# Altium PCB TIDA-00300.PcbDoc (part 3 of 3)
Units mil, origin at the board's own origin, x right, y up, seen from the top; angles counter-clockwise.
Board outline 2685 x 3089 mil, 4 copper layers (Top Layer, L2_GND-PLANE, L3_PWR-PLANE, Bottom Layer), stack 63.6 mil thick; 196 components, 87 nets, 476 pads, 171 vias.
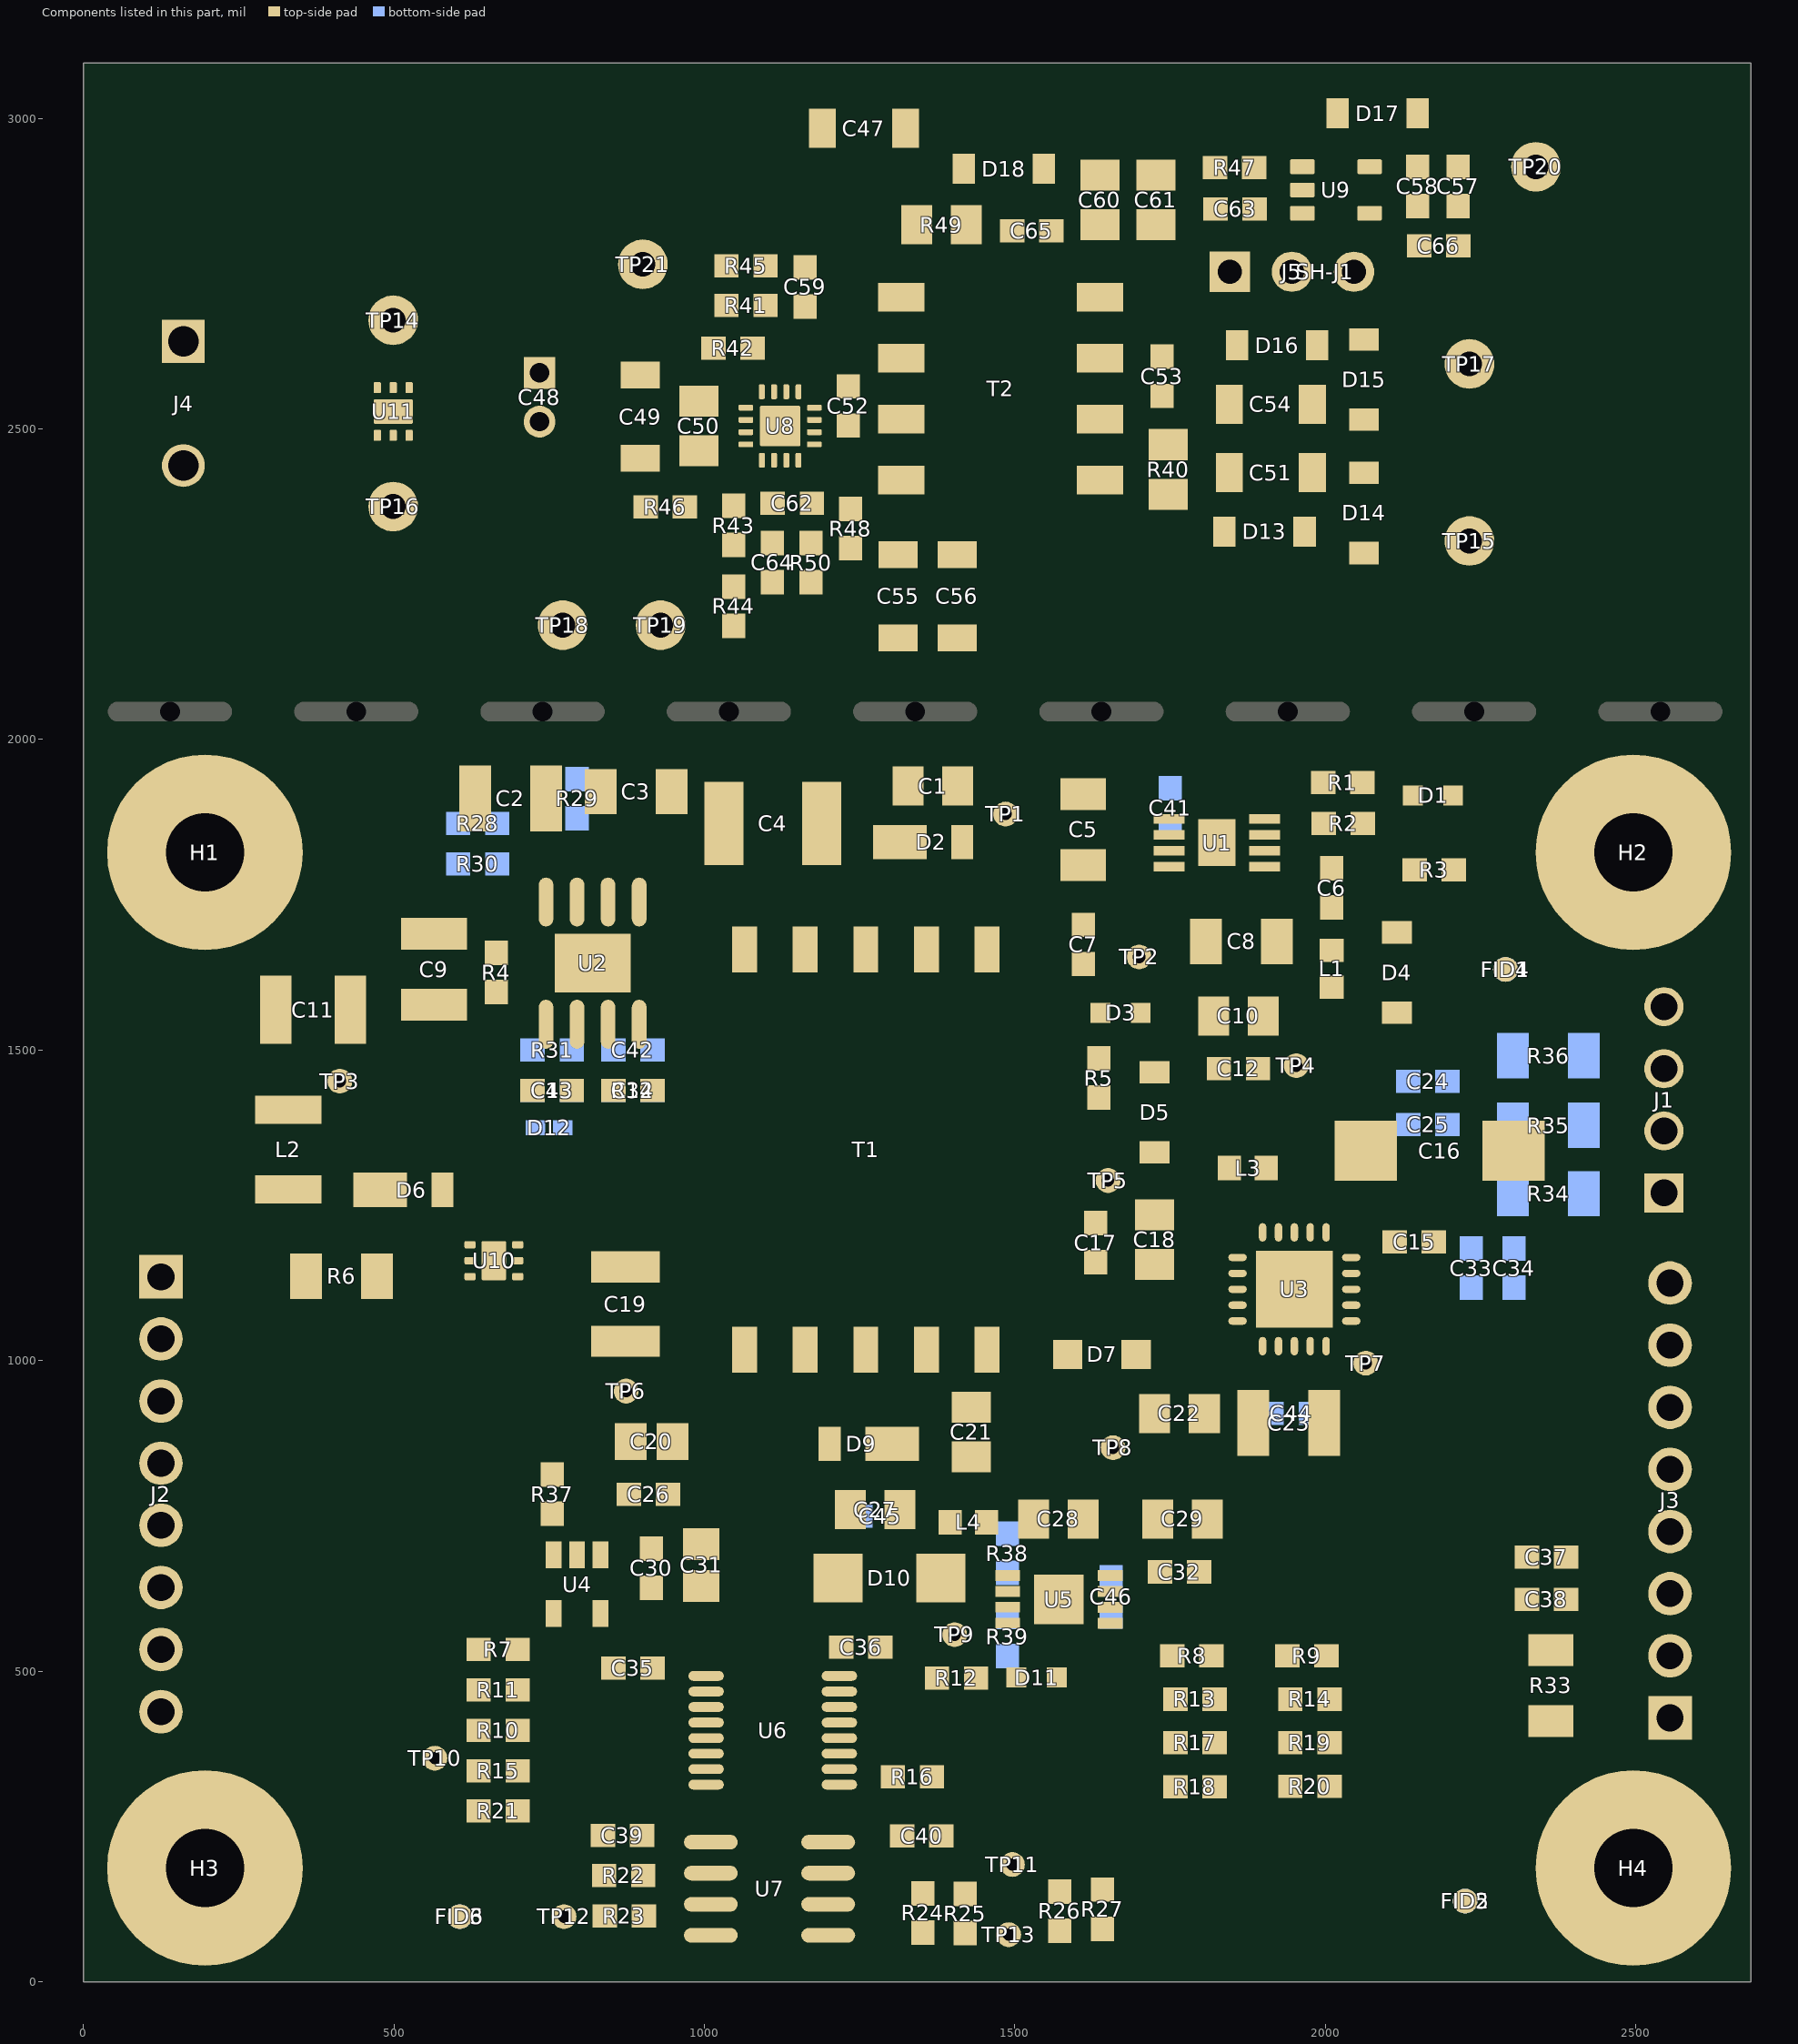
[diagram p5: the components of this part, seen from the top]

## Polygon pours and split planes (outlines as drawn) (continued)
GND_ISO on Top Layer "Top Layer-No Net 1" (hatched 90Degree grid 5 track 10, remove dead copper, pour order 64): 1830,1415 1705,1415 1700,1420 1700,1595 1760,1655 1760,1700 1800,1740 1800,1885 1770,1915 1579,1915 1579,1955 1840,1955 1855,1940 1855,1650 1840,1635 1840,1425
+6V_ISO on Top Layer "Top Layer-No Net 1" (hatched 90Degree grid 5 track 10, remove dead copper, pour order 58): 1635,565 1725,565 1755,595 1755,1043 1743,1055 1680,1055 1665,1040 1665,945 1625,905 1625,820 1660,785 1660,730 1690,700 1690,675 1685,670 1635,670 1635,650 1725,650 1735,640 1735,600 1715,580 1635,580
GND_ISO on Top Layer "Top Layer-No Net 1" (hatched 90Degree grid 5 track 10, remove dead copper, pour order 65): 1595,465 1555.67,465 1545,475.67 1545,535 1520,560 1465,560 1460,565 1460,575 1465,580 1525,580 1535,590 1535,655 1590,710 1590,770 1620,770 1620,710 1600,690 1600,470
9.3V_NON_ISO on Top Layer "Top Layer-No Net" (hatched 90Degree grid 5 track 8, remove dead copper, pour order 67): 1075,1040 1010,1040 987,1027 962,1027 935,1054 786,1053 786,801 820,759 820,670 830,660 855,660 865,670 865,730 895,760 895,910 910,925 955,925 1030,1000 1070,1000 1075,1005
GND on Top Layer "Bottom Layer-No Net" (solid, remove dead copper, pour order 40): 663,1277 647,1261 647,1116 655,1108 955,1108 966,1119 966,1255 944,1277
GND on Top Layer "Bottom Layer-No Net" (solid, remove dead copper, pour order 44): 510,1600 510,1470 510,1460 520,1450 530,1440 625,1440 660,1440 680,1420 680,1395 690,1385 735,1385 745,1395 750,1400 750,1465 750,1470 720,1500 715,1505 685,1505 675,1505 625,1555 620,1560 620,1595 620,1600 615,1605 515,1605 510,1600
+24VDC_LIMIT on Top Layer "Bottom Layer-No Net" (solid, remove dead copper, pour order 43): 382,1090 388,1096 388,1177 379,1185 80,1185 70,1170 70,1090
NetC2_2 on Top Layer "Bottom Layer-No Net" (solid, remove dead copper, pour order 49): 440,1375 265,1375 245,1395 245,1430 305,1490 355,1490 375,1510 375,1650 525,1825 660,1825 690,1855 690,1955 705,1970 855,1970 870,1955 870,1790 855,1775 855,1715 850,1710 835,1710 835,1715 830,1720 830,1810 810,1830 765,1830 715,1780 695,1780 620,1705 620,1660 595,1635 515,1635 485,1605 485,1420
+5V_ISO on Top Layer "Bottom Layer-No Net" (solid, remove dead copper, pour order 87): 2325,505 2325,560 2325,565 2335,575 2340,580 2350,580 2360,580 2370,590 2370,620 2370,725 2385,740 2450,740 2465,725 2475,715 2475,650 2475,540 2445,510 2440,505 2325,505
GND_ISO on Top Layer "Bottom Layer-No Net" (solid, remove dead copper, pour order 89): 2265,710 2340,710 2345,705 2345,630 2345,600 2335,590 2275,590 2260,590 2245,605 2245,665 2245,700 2255,710 2265,710
+5V_ISO on Top Layer "Top Layer-No Net 1" (hatched 90Degree grid 5 track 10, remove dead copper, pour order 63): 1402.68,775 1410,767.68 1410,705 1445,670 1445,630 1445,589 1444,563 1435,550 1430,545 1385,545 1335,595 1335,690 1300,725 1300,760 1315,775
GND_ISO on Bottom Layer "Top Layer-No Net 1" (hatched 90Degree grid 5 track 10, remove dead copper, pour order 151): 1200,45 2628,40 2638,50 2634.75,66 2630,105 2650,165 2650.5,261 2648,360 2645,416 2645,1970 1175,1965 1165,1955 1165,1710 1150,1710 1150,1635 1515,1635 1530,1620 1530,1060 1515,1045 1150,1045 1150,985 1185,985 1185,60
9.3V_NON_ISO on Bottom Layer "Bottom Layer-No Net" (solid, remove dead copper, pour order 50): 800,785 885,785 900,800 900,835 900,1015 855,1060 850,1065 850,1130 850,1160 805,1205 740,1270 740,1285 740,1495 725,1510 695,1510 690,1510 670,1490 670,1435 670,1065 750,985 790,945 790,915 790,795 800,785
+5V_ISO on Bottom Layer "Top Layer-No Net 1" (hatched 90Degree grid 5 track 10, remove dead copper, pour order 77): 1305,775 1305,630 1390,545 1440,545 1455,560 1455,765 1440,780 1310,780
GND on Bottom Layer "Bottom Layer-No Net" (solid, remove dead copper, pour order 51): 50,25 50,1950 235,1965 1040,1965 1065,1949 1065,1711 1084,1711 1085,1631 979,1631 979,1046 986,1039 1075,1039 1085,1029 1085,978 1045,978 1045,49 1025,29 596,29 530,30
+15V_ISO on Bottom Layer "Bottom Layer-No Net" (solid, remove dead copper, pour order 81): 2196,1312 2199,1315 2320,1315 2330,1305 2330,1265 2330,1170 2320,1160 2225,1160 2170,1160 2160,1170 2155,1175 2155,1300 2155,1305 2160,1310 2165,1315 2200,1315
GND_ISO on Bottom Layer "Bottom Layer-No Net" (solid, remove dead copper, pour order 85): 2190,1135 2255,1135 2335,1135 2350,1135 2360,1145 2365,1150 2365,1175 2365,1190 2380,1205 2435,1205 2460,1205 2470,1195 2470,1150 2470,1105 2400,1035 2390,1025 2290,1025 2210,1025 2185,1050 2185,1130 2190,1135
-15V_ISO on Bottom Layer "Bottom Layer-No Net" (solid, remove dead copper, pour order 83): 2285,1415 2325,1415 2335,1405 2335,1350 2325,1340 2195,1340 2180,1360 2180,1470 2140,1525 2068.43,1526 2056.86,1506 2056.19,1456 2033,1431 1953,1430 1933,1450 1933,1575 1958,1600 2118,1600
GND_ISO on L3_PWR-PLANE "Top Layer-No Net 1" (hatched 90Degree grid 5 track 10, remove dead copper, pour order 76): 1980,1175 1565,1175 1545,1150 1544.54,1111 1544,1109 1545,1055 1520,1030 1215,1030 1195,1010 1195,805 1230,770 1390,770 1410,790 1410,885 1485,960 2075,960 2095,990 2095,1060
+15V_ISO on L3_PWR-PLANE "Bottom Layer-No Net" (solid, remove dead copper, pour order 45): 2065,1160 2230,1160 2305,1225 2305,1270 2279,1296 1940,1296 1830,1406 1555,1406 1535,1386 1535,1233 1565,1210 2000,1210
+5V_ISO on L3_PWR-PLANE "Top Layer-No Net 1" (hatched 90Degree grid 5 track 10, remove dead copper, pour order 75): 1190,730 1185,705 1185,75 1220,40 2572.86,32 2640,105 2640,1150 2615,1185 2465,1185 2460.37,1185.07 2400,1185 2335,1185 2135,980 2135,835 2025,730
+18V_ISO on L3_PWR-PLANE "Top Layer-No Net 1" (hatched 90Degree grid 5 track 10, remove dead copper, pour order 52): 2020,810 1990,780 1515,780 1480,815 1480,895 1510,925 1995,925 2020,900
+3.3V_NON_ISO on L3_PWR-PLANE "Top Layer-No Net" (hatched 90Degree grid 5 track 8, remove dead copper, pour order 73): 1025,665 1040,650 1040,45 1025,30 605,30 560,75 560,525 680,635 705,660 714.31,665.99 735,665
-15V_ISO on L3_PWR-PLANE "Bottom Layer-No Net" (solid, remove dead copper, pour order 48): 1940,1340 2295,1340 2320,1370 2320,1535 2215,1640 2215,1910 2165,1960 1640,1960 1540,1860 1540,1450 1560,1430 1855,1430 1940,1345
GND_iso_1 on L2_GND-PLANE "vdd" (solid, remove dead copper, pour order 129): 1277,2675.43 1293.43,2659 1500,2659 1512,2647 1512,2123 1530,2105 2593,2105 2644,2156 2644,3026 2606,3064 1284,3064 1277,3057
DGND_1 on L2_GND-PLANE "vdd" (solid, remove dead copper, pour order 127): 1234,2592 1239,2587 1425,2587 1455,2557 1455,2128 1432,2105 103,2105 58,2150 58,3025 97,3064 1230,3064 1234,3060
GND_ISO on L2_GND-PLANE "Top Layer-No Net 1" (hatched 90Degree grid 5 track 10, remove dead copper, pour order 55): 1200,45 2628,40 2638,50 2634.75,66 2630,105 2650,165 2650.5,261 2648,360 2645,416 2645,1970 1175,1965 1165,1955 1165,1710 1150,1710 1150,1635 1515,1635 1530,1620 1530,1060 1515,1045 1150,1045 1150,985 1185,985 1185,60
GND on L2_GND-PLANE "Top Layer-No Net" (hatched 90Degree grid 5 track 8, remove dead copper, pour order 74): 1030,35 145,35 50,125 50,1965 1055,1965 1060,1955 1060,1700 1075,1700 1075,1635 990,1635 975,1620 975,1055 990,1040 1066,1040 1075,1031 1075,985 1070,980 1045,980 1035,970 1035,40

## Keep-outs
Keep-Out Layer:
  text ".Layer_Name" at 772,-858.49 h60

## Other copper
Top Layer:
  region: 1952.5,2886
  text ".Layer_Name" at 772,-858.49 h60
L2_GND-PLANE:
  pour cut-out: 1237,2594.67 1237,2644.67 1506.85,2644.67 1506.85,2594.67
  pour cut-out: 1275,2594.67 1237,2594.67 1237,3089 1275,3089
  pour cut-out: 1457,2644.67 1507,2644.67 1507,2100 1457,2100
  pour cut-out: 2585,270 2585,210 2616.5,210 2620,206.5 2620,265 2615,270
  text ".Layer_Name" at 807,-866 h60
L3_PWR-PLANE:
  pour cut-out: 2351.78,40.97 2351.78,56.22 2298,110 2298,265 2304.88,265 2414.88,375 2585,375 2665,295 2665,55 2630,20 2372.75,20
  text ".Layer_Name" at 835,-860 h60
Bottom Layer:
  pour cut-out: 1476.4,538.6 1476.79,539 1514,539 1514,562.95 1515,563.95 1515,730 1510,735 1482,735 1482,542 1476,536
  pour cut-out: 787,1834 676,1834 674,1836 674,1966 684,1976 768,1976 769,1975 769,1889 787,1871
  pour cut-out: 700,1750 700,1845 695,1850 580,1850 573,1843 573,1750.07 578.07,1745 695,1745
  pour cut-out: 1615,691 1615,611 1626,600 1668,600 1690,578 1690,576 1725,576 1738,589 1738,663 1701,700 1624,700
  pour cut-out: 1713,1890 1713,1815 1723,1805 1778,1805 1788,1815 1788,1884.89 1777.89,1895 1718,1895
  text ".Layer_Name" at 772,-858.49 h60
Multi-Layer:
  pour cut-out: 1046.18,0 1173.35,0 1173,976 1142,976 1142,1055 1518.78,1055 1518.78,1620 1142,1620 1143,1716 1158,1716 1155,1891 1156,1941 1158,1999 1140,2000 1065,2000 1065,1711 1084,1711 1085,1620 991.22,1620 991.22,1055 1085,1055 1085,978 1045,978

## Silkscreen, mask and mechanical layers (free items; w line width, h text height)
Top Overlay:
  circle w6: c272.93,1140 r7.07
  circle w6: c2020,1206 r2.24
  circle w10: c2380,1265 r5
  circle w10: c2595,345 r5
  circle w11: c864,685 r5
  lines w6: 850,2417 1071.89,2417 1081.63,2407.27 ; 1064,2797 1064,2819 ; 1175,590 1182.28,590 1195.02,577.27 ; 1465,780 1465,781 1485,801 ; 1500,542.4 1635,542.4 ; 1500,689.2 1635,689.2 ; 1529,199 1535,205 ; 1561,2977 1561,3010 ; 1707,1815 1707,1760.2 1942,1760.2 1942,1905.2 1707,1905.2 1707,1860 ; 1850,2142 1850,2269 ; 1852,2951 1852,2984 ; 1950,1910 1951.28,1910 1969.02,1892.27 ; 2045,435 2067,435 ; 2249,2880 2292,2837 2315,2837 ; 2305,300 2280,275 2080,275 2067,288 2067,552 2080,565 2300,565 2305,560 ; 1064,2819 1065,2819 1070,2814 1059,2814 1064,2819 ; 1561,3010 1568,3003 1554,3003 1561,3010 ; 1695,45 1680,30 1305,30 1280,55 1280,175 1290,185 1295,185 1445,185 1475,155 1510,155 1545,190 1675,190 1695,170 ; 1695,45 1695,170 ; 1695,45 1705,35 1980,35 2000,55 2000,165 1980,185 1710,185 1695,170 ; 1850,2269 1857,2262 1843,2262 1850,2269 ; 1852,2984 1845,2977 1859,2977 1852,2984 ; 2315,2837 2315,2836.4 2309,2830.4 2309,2843 2315,2837 ; 1700,295 1700,555 1710,565 2035,565 2045,555 2045,280 2035,270 1725,270 1700,295
  lines w7.87: 1320,509 1363,552
  lines w10: -0.47,2044 2684.53,2044
  text "TIDA-0300" at 263,764 h50
  text "Rev-E3" at 311,691 h50
  text ".Layer_Name" at 772,-858.49 h35
Bottom Overlay:
  text ".Layer_Name" at 772,-858.49 h35
Top Paste:
  text ".Layer_Name" at 772,-858.49 h60
Bottom Paste:
  text ".Layer_Name" at 772,-858.49 h60
Top Solder:
  text ".Layer_Name" at 772,-858.49 h60
  text ".Layer_Name" at 772,-858.49 h60
Bottom Solder:
  text ".Layer_Name" at 772,-858.49 h60
Drill Guide:
  text ".Layer_Name" at 772,-858.49 h60
M1 Board Outline:
  the board outline again, w10
M2 Board Dimensions:
  rectangle: 319.5,-410.5 694.5,-285.5
  rectangle: 194.5,-285.5 319.5,-160.5
  lines w7: 194.5,-285.5 1194.5,-285.5 ; 319.5,-410.5 319.5,-160.5 ; 444.5,-410.5 444.5,-160.5 ; 694.5,-410.5 694.5,-160.5 ; 944.5,-410.5 944.5,-160.5 ; 194.5,-410.5 194.5,-160.5 1194.5,-160.5 1194.5,-410.5 194.5,-410.5
  lines w10: 194.5,-475.5 194.5,-455.5 ; 254.5,-485.5 194.5,-465.5 ; 254.5,-445.5 194.5,-465.5 ; 418.58,-465.5 194.5,-465.5 ; 970.42,-465.5 1194.5,-465.5 ; 1134.5,-485.5 1194.5,-465.5 ; 1134.5,-445.5 1194.5,-465.5 ; 1194.5,-475.5 1194.5,-455.5
  text "1000 (mil)" at 428.58,-501.49 h60
M3 3D STEP Top:
  text ".Layer_Name" at 772,-858.49 h60
M4 3D STEP Bottom:
  text ".Layer_Name" at 772,-858.49 h60
M5 Assembly Top:
  circle w6: c982,492 r5.33
  circle w6: c1944,2921 r6.71
  circle w6: c280,1140 r8
  circle w6: c2605,345 r10
  circle w15: c833,727 r6
  lines w6: 1393.5,712.32 1456.5,712.32 ; 1393.5,767.68 1456.5,767.68 ; 1500,435 1525,435 ; 1523.58,474.25 1546.42,474.25 ; 1523.58,505.75 1546.42,505.75 ; 1550,410 1550,460 ; 1575,435 1550,435 ; 1635.5,1602 1660.5,1602 ; 1680,1584 1680,1624 ; 1704,1603 1679,1603 ; 1843.5,1282.32 1906.5,1282.32 ; 1843.5,1337.68 1906.5,1337.68 ; 1982.32,1599.5 1982.32,1662.5 ; 2037.68,1599.5 2037.68,1662.5 ; 2161.58,1894.25 2184.42,1894.25 ; 2161.58,1925.75 2184.42,1925.75 ; 2229.79,1910.04 2254.79,1910.04 ; 2278,1911.83 2254.79,1935.04 2254.79,1885.04 2279.79,1910.04 ; 2279.79,1885.04 2279.79,1935.04 ; 2283,1910.04 2304.79,1910.04 ; 1550,435 1525,460 1525,410 1550,435 ; 1679,1603 1662,1586 1660.5,1587.5 1660.5,1621.5 1679,1603
  lines w10: -97,-930.17 6503,-930.17 ; -97,-726.83 6505,-726.83 ; -97,-523.5 -97,-1133.5 3908,-1133.5 6505,-1133.5 6505,-523.5 -96.5,-523.5 -96.5,-1133.5 1479,-1133.5 ; 2368,-1133.5 2368,-523.5 ; 3930,-726 3930,-522.67 ; 4475,-726.83 4475,-523.5 ; 5097,-1140 5097,-937.17
  text "D1" at 2157,1938 h30
  text "L1" at 2025,1611 h30 r90
  text "J1" at 2343,1346 h40
  text "L3" at 1852,1295 h30
  text "L4" at 1398.39,724.14 h35
  text "D11" at 1582,475 h30
  text "COMPONENTS MARKED 'DNP' SHOULD NOT BE POPULATED." at 1348.5,-318.5 h40
  text "ASSEMBLY VARIANT:" at 1348,-434 h40
  text ".VariantName" at 2384,-434 h40
  text "REV:" at 4001,-648 h20
  text ".PCB_Rev" at 4094.22,-648.74 h20
  text "PCB VIEWED FROM TOP SIDE" at -33.5,-655.67 h40
  text "SVN REV:" at 4671,-655.67 h40
  text ".VersionControl_RevNumber" at 5177,-655.67 h40
  text "BOARD #:" at 2464.72,-686.74 h20
  text ".PRJ_Number" at 3010.22,-686.74 h20
  text ".Layer_Name" at 789,-846.98 h20
  text "LAYER NAME =" at -8.78,-849.56 h20
  text "TID #:" at 2463.72,-852.07 h20
  text ".TID" at 3009.22,-852.07 h20
  text "PLOT NAME =" at -33.5,-1064.34 h40
  text ".plot_File_Name" at 772,-1064.34 h40
  text "GENERATED    :" at 2445,-1064.34 h40
  text ".Print_Date" at 3314.5,-1064.34 h40
  text ".Print_Time" at 4043.5,-1064.34 h40
  text "TEXAS INSTRUMENTS" at 5308,-1064.34 h40
M6 Assembly Bottom:
  lines w10: -97.5,-727.33 6504.5,-727.33 ; -95.5,-930.67 6504.5,-930.67 ; 1310.5,-1140.5 1310.5,-937.67 ; 1932.5,-727.33 1932.5,-524 ; 2431,-723 2431,-519.67 ; 4039.5,-1134 4039.5,-524 ; 4928.5,-1134 6504,-1134 6504,-524 -97.5,-524 -97.5,-1134 2499.5,-1134 6504.5,-1134 6504.5,-524
  text "COMPONENTS MARKED 'DNP' SHOULD NOT BE POPULATED." at 6297,-318 h60
  text ".VariantName" at 5253,-434 h60
  text "ASSEMBLY VARIANT:" at 6292,-434 h60
  text "REV:" at 2320.28,-652.41 h60
  text ".PRJ_Number" at 3637,-652 h40
  text ".VersionControl_RevNumber" at 1230.5,-656.17 h60
  text "SVN REV:" at 1736.5,-656.17 h60
  text ".PCB_Rev" at 2071.28,-656.41 h60
  text "BOARD #:" at 3961.5,-655.67 h40
  text "PCB VIEWED FROM BOTTOM SIDE" at 6441,-656.17 h60
  text ".Layer_Name" at 5464,-845.98 h20
  text "LAYER NAME =" at 6261.78,-848.56 h20
  text ".TID" at 3416,-859 h60
  text "TID #:" at 3961.5,-859 h60
  text "TEXAS INSTRUMENTS" at 1099.5,-1064.84 h60
  text ".Print_Time" at 2364,-1064.84 h60
  text ".Print_Date" at 3093,-1064.84 h60
  text "GENERATED    :" at 3962.5,-1064.84 h60
  text ".plot_File_Name" at 5635.5,-1064.84 h60
  text "PLOT NAME =" at 6441,-1064.84 h60
M9 Title Sheet:
  drawing of 57 lines, arcs and shapes, not listed
  text "1" at 934.84,8036.5 h70
  text "2" at 3430.5,8036.5 h70
  text "3" at 5919.84,8036.5 h70
  text "4" at 8426.51,8036.5 h70
  text "5" at 10925.5,8036.5 h70
  text "6" at 13430.5,8036.5 h70
  text "A" at -221.5,6893.5 h70
  text "A" at 14578.5,6893.5 h70
  text "B" at -221.5,4513.5 h70
  text "B" at 14578.5,4513.5 h70
  text "C" at -221.5,2138.5 h70
  text "C" at 14578.5,2138.5 h70
  text "PROJECT TITLE:" at 11538.5,277.5 h45
  text "TIDA-00300 Isolated PS and comm.Interface" at 11588.5,144.17 h70
  text "DESIGNED FOR:" at 11538.5,-23.5 h45
  text ".PRJ_Customer" at 11588.5,-163.5 h70
  text "D" at -221.5,-231.5 h70
  text "D" at 14578.5,-231.5 h70
  text "FILE NAME:" at 11538.5,-323.5 h45
  text "TIDA-00300" at 11588.5,-443.5 h70
  text "Texas Instruments (TI) and/or its licensors do not warrant the accuracy or completeness of this specification" at 6569,-605.34 h45
  text "ENGINEER:" at 11538.5,-613.5 h45
  text "LAYOUT BY:" at 13043.5,-613.5 h45
  text "or any information contained therein. TI and/or its licensors do not warrant that this design will meet" at 6524.01,-718 h45
  text ".PCB_Layout" at 13050.72,-754.73 h70
  text ".PRJ_Engineer" at 11588.5,-768.49 h70
  text "the specifications, will be suitable for your application or fit for any particular purpose, or will operate in" at 6524.01,-830.67 h45
  text "ALTIUM DESIGNER VERSION:" at 13043.5,-923.5 h45
  text "an implementation. TI and/or its licensors do not warrant that the design is production worthy. You should" at 6524.01,-943.33 h45
  text "completely validate and test your design implementation to confirm the system functionality for your application." at 6569,-1056 h45
  text ".print_Scale" at 11588.5,-1056.83 h70
  text ".Application_BuildNumber" at 13094,-1056.83 h70
  text "1" at 934.84,-1263.5 h70
  text "2" at 3430.5,-1263.5 h70
  text "3" at 5919.84,-1263.5 h70
  text "4" at 8426.51,-1263.5 h70
  text "5" at 10925.5,-1263.5 h70
  text "6" at 13430.5,-1263.5 h70
M10 Fab Notes:
  drawing of 220 lines, arcs and shapes, not listed
  text "DESIGN INFORMATION" at 12576.02,6810 h60
  text "(REFER ALSO ARRAY/PANEL PROFILING INFORMATION)" at 12214.46,6648.29 h60
  text "BOARD SIZE" at 11528.46,6644 h60
  text "68.20MM" at 11990.78,6516.18 h60
  text "X" at 12496.46,6516.18 h60
  text "78.46MM" at 12727.78,6516.18 h60
  text "Number of Layers :" at 11946.46,6409 h60
  text "4" at 13041.27,6399 h60
  text "MIN. TRACK WIDTH:" at 11946.46,6270 h60
  text "8" at 13042.7,6270 h60
  text "MIL" at 13197.46,6270 h60
  text "7.87" at 12947,6141 h60
  text "MIN. CLEARANCE:" at 11946.46,6138 h60
  text "MIL" at 13197.46,6138 h60
  text "MIN. VIA PAD SIZE:" at 11946.46,6006 h60
  text "24" at 13012.71,6006 h60
  text "MIL" at 13197.46,6006 h60
  text "0.152mm (6MIL)" at 12641.46,5864.29 h60
  text "EXTERNAL" at 13392,5862 h60
  text "MINIMUM ANNULAR RING" at 11617.23,5860 h60
  text "PER" at 11817.23,5742 h60
  text "IPC-D-275 CLASS 2 LEVEL C" at 12037.23,5742 h60
  text "MIL, HOLES" at 13525.46,5629.71 h60
  text "+/-" at 13133,5629 h60
  text "+/-" at 13987,5629 h60
  text "REGISTRATION TOLERANCES:" at 11617.23,5624 h60
  text "METAL" at 12817,5624 h60
  text "5" at 13393.2,5624 h60
  text "3" at 14226.2,5624 h60
  text "MIL" at 14342.46,5624 h60
  text "IMPEDENCE CONTROLLED BOARD:NO" at 11650,5475 h60
  text "MATERIAL:" at 11527.46,5324.54 h60
  text "X" at 12360,5186 h60
  text "FR-4 High Tg" at 12513.9,5184.21 h60
  text "FR-408" at 11948.46,5175.64 h60
  text "OTHER" at 13436.46,5175.64 h60
  text "63 MIL (1.6mm) +/-10%" at 12268.56,5012.92 h60
  text "THICKNESS:" at 11602.23,5008.64 h60
  text "X" at 12140.4,5008.64 h60
  text "OTHER" at 13553.46,5008.64 h60
  text "TOLERANCE:" at 11602.23,4850.64 h60
  text "X" at 12441.53,4850.64 h60
  text "ANSI IPC-6012 TYPE 3 CLASS 2" at 12628.48,4850.64 h60
  text "OTHER +/-" at 12628.46,4694.64 h60
  text "BOW & TWIST:" at 11602.23,4537.64 h60
  text "X" at 12441.53,4537.64 h60
  text "ANSI IPC-6012 TYPE 3 CLASS 2" at 12628.48,4537.64 h60
  text "OTHER +/-" at 12628.46,4379.13 h60
  text "COPPER THICKNESS (FINISHED):" at 11527.46,4243.64 h60
  text "1.4MIL (1oz)" at 12407.46,4090.92 h60
  text "2MIL (1.4oz)" at 13174.46,4090.92 h60
  text "2.8MIL (2oz)" at 13901.46,4090.92 h60
  text "OUTER:" at 11884.46,4086.64 h60
  text "X" at 12279,4086 h60
  text "1.4MIL (1oz)" at 12407.46,3933.92 h60
  text "2.8MIL (2oz)" at 13174.46,3933.92 h60
  text "N/A" at 13901,3934.29 h60
  text "INNER SIGNAL:" at 11595.38,3929.64 h60
  text "X" at 12280.42,3929.64 h60
  text "DRILLING:" at 11527.46,3790.64 h60
  text "REFERENCE:" at 11602.23,3673.64 h60
  text "X" at 12250.46,3673.64 h60
  text "AS SHOWN" at 12437.46,3673.64 h60
  text "X" at 13151.46,3673.64 h60
  text "NC_DRILL FILES" at 13288.46,3673.64 h60
  text "PTH MIN COPPER THICKNESS:" at 11602.23,3515.64 h60
  text "X" at 12952.46,3515.64 h60
  text "1MIL" at 13089.46,3515.64 h60
  text "OTHER" at 13586.46,3515.64 h60
  text "BOARD FINISH:" at 11527.46,3356.64 h60
  text "SILKSCREEN:" at 11682.68,3238.64 h60
  text "X" at 12631.46,3238.64 h60
  text "TOP" at 12757.46,3238.64 h60
  text "X" at 13141.46,3238.64 h60
  text "BOTTOM" at 13268.46,3238.64 h60
  text "SILKSCREEN COLOR:" at 11681.01,3072.64 h60
  text "X" at 12628.75,3072.64 h60
  text "WHITE" at 12755.79,3072.64 h60
  text "OTHER" at 13266.79,3072.64 h60
  text "SOLDER RESIST COLOR:" at 11787.01,2921.64 h60
  text "GREEN" at 12481.79,2762.44 h60
  text "X" at 12244,2750 h60
  text "BLUE" at 13052,2744 h60
  text "OTHER" at 13501,2740 h60
  text "IMMERSION GOLD (ENIG)" at 12588.46,2553.92 h60
  text "ENEPIG" at 13926,2550.64 h60
  text "SURFACE FINISH:" at 11527.46,2549.64 h60
  text "X" at 12401.51,2549.64 h60
  text "IMM. TIN/SILVER OR EQUIV" at 11857,2392.64 h60
  text "OTHER" at 13288.46,2392.64 h60
  text "ARRAY/PANEL:" at 11527.46,2213.64 h60
  text "CUT AND TRIM PER MECH LAYER 1" at 12588.46,2209.35 h60
  text "N.C. ROUTE" at 12588.46,2057.64 h60
  text "X" at 13267.46,2057.64 h60
  text "V. SCORE" at 13454.46,2057.64 h60
  text "CERTIFICATION:" at 11527.46,1920.64 h60
  text "MATERIALS AND WORKMANSHIP FOR ALL PCBS" at 12252.46,1920.64 h60
  text "TO MEET OR EXCEED THE REQUIREMENTS OF:" at 12252.46,1822.64 h60
  text "X" at 11878.96,1686.13 h60
  text "ANSI IPC-A-600F CLASS ->" at 12017.96,1686.13 h60
  text "X" at 13657.02,1686.13 h60
  text "2" at 13775.96,1686.14 h60
  text "1" at 13460.96,1684.64 h60
  text "3" at 14129.96,1684.64 h60
  text "X" at 11881.02,1526.64 h60
  text "UL 94V-0" at 12017.96,1526.64 h60
  text "X" at 12693.02,1526.64 h60
  text "RoHS" at 12829.96,1526.64 h60
  text "OTHER" at 13474.36,1526.64 h60
  text "PER ORDER" at 13871.42,1526.64 h60
  text "ADDITIONAL REQUIREMENTS:" at 11527.46,1385.64 h60
  text "VIA TENTING:" at 13002,1292.36 h60
  text "X" at 13790.29,1292.48 h60
  text "YES" at 13573.67,1283.28 h60
  text "NO" at 13968.47,1283.05 h60
  text "MICROSECTION:" at 11602.23,1270.64 h60
  text "YES" at 12507.96,1270.64 h60
  text "REQUIRED" at 13369.46,1114.49 h60
  text "BARE BOARD ELEC. TEST:" at 11602.23,1111.64 h60
  text "NONE" at 12907.96,1111.64 h60
  text "X" at 13242.46,1111.64 h60
  text "PER ORDER" at 13961.46,1111.64 h60
  text "MANUFACTURER'S UL:" at 11602.23,954.64 h60
  text "RAIL" at 12767.96,950.35 h60
  text "METAL" at 13259.77,950.35 h60
  text "X" at 13635,950 h60
  text "SILK" at 13771.46,950.35 h60
M11 Gerber Information:
  lines w10: -97,-930.17 6503,-930.17 ; -97,-726.83 6505,-726.83 ; -97,-523.5 -97,-1133.5 3908,-1133.5 6505,-1133.5 6505,-523.5 -96.5,-523.5 -96.5,-1133.5 1479,-1133.5 ; 2368,-1133.5 2368,-523.5 ; 3885,-730 3885,-526.67 ; 4475,-726.83 4475,-523.5 ; 5097,-1140 5097,-937.17
  text "ALL ARTWORK VIEWED FROM TOP SIDE" at -33.5,-655.67 h60
  text "BOARD #:" at 2443,-655.67 h60
  text ".PRJ_Number" at 2935,-656.41 h60
  text "SVN REV:" at 4671,-655.67 h60
  text ".VersionControl_RevNumber" at 5177,-655.67 h60
  text "REV: E3" at 3980,-657 h60
  text "TID #:" at 2503.72,-856.07 h60
  text ".TID" at 3049.22,-856.07 h60
  text "LAYER NAME =" at -33.5,-858.49 h60
  text "PLOT NAME =" at -33.5,-1064.34 h60
  text ".plot_File_Name" at 772,-1064.34 h60
  text "GENERATED    :" at 2445,-1064.34 h60
  text ".Print_Date" at 3314.5,-1064.34 h60
  text ".Print_Time" at 4043.5,-1064.34 h60
  text "TEXAS INSTRUMENTS" at 5308,-1064.34 h60
M12 Stackup:
  drawing of 295 lines, arcs and shapes, not listed
  text "Layer" at 4531.5,5013.5 h60
  text "Name" at 4941.41,5013.5 h60
  text "Material" at 5871.16,5013.5 h60
  text "Thickness" at 6730.92,5013.5 h60
  text "Constant" at 7380.76,5013.5 h60
  text "Board Layer Stack" at 7950.62,5013.5 h60
  text "1" at 4531.5,4893.5 h60
  text "Top Overlay" at 4941.41,4893.5 h60
  text "2" at 4531.5,4773.5 h60
  text "Top Solder" at 4941.41,4773.5 h60
  text "Solder Resist" at 5871.16,4773.5 h60
  text "0.40mil" at 6730.92,4773.5 h60
  text "3.5" at 7380.76,4773.5 h60
  text "3" at 4531.5,4653.5 h60
  text "Top Layer" at 4941.41,4653.5 h60
  text "Copper" at 5871.16,4653.5 h60
  text "1.40mil" at 6730.92,4653.5 h60
  text "4" at 4531.5,4533.5 h60
  text "Dielectric1" at 4941.41,4533.5 h60
  text "FR-4 High Tg" at 5871.16,4533.5 h60
  text "23.00mil" at 6730.92,4533.5 h60
  text "4.8" at 7380.76,4533.5 h60
  text "5" at 4531.5,4413.5 h60
  text "L2_GND-PLANE" at 4941.41,4413.5 h60
  text "Copper" at 5871.16,4413.5 h60
  text "1.40mil" at 6730.92,4413.5 h60
  text "6" at 4531.5,4293.5 h60
  text "Dielectric2" at 4941.41,4293.5 h60
  text "FR-4 High Tg" at 5871.16,4293.5 h60
  text "12.00mil" at 6730.92,4293.5 h60
  text "4.8" at 7380.76,4293.5 h60
  text "7" at 4531.5,4173.5 h60
  text "L3_PWR-PLANE" at 4941.41,4173.5 h60
  text "Copper" at 5871.16,4173.5 h60
  text "1.40mil" at 6730.92,4173.5 h60
  text "8" at 4531.5,4053.5 h60
  text "Dielectric3" at 4941.41,4053.5 h60
  text "FR-4 High Tg" at 5871.16,4053.5 h60
  text "23.00mil" at 6730.92,4053.5 h60
  text "4.8" at 7380.76,4053.5 h60
  text "9" at 4531.5,3933.5 h60
  text "Bottom Layer" at 4941.41,3933.5 h60
  text "Copper" at 5871.16,3933.5 h60
  text "1.40mil" at 6730.92,3933.5 h60
  text "10" at 4531.5,3813.5 h60
  text "Bottom Solder" at 4941.41,3813.5 h60
  text "Solder Resist" at 5871.16,3813.5 h60
  text "0.40mil" at 6730.92,3813.5 h60
  text "3.5" at 7380.76,3813.5 h60
  text "11" at 4531.5,3693.5 h60
  text "Bottom Overlay" at 4941.41,3693.5 h60
M13 Component Bodies Top:
  text ".Layer_Name" at 772,-858.49 h60
M14 Component Bodies Bottom:
  text ".Layer_Name" at 772,-858.49 h60
M15 Courtyards Top:
  text ".Layer_Name" at 772,-858.49 h60
M16 Courtyards Bottom:
  text ".Layer_Name" at 772,-858.49 h60
Drill Drawing:
  circle w10: c4064.62,3044.27 r20
  circle w10: c4064.62,3044.27 r33.33
  circle w10: c4064.62,1694.28 r33.33
  lines w10: 4031.29,1360.94 4097.96,1360.94 4097.96,1427.61 4031.29,1427.61 4031.29,1360.94 ; 4031.29,1577.61 4097.96,1577.61 4064.62,1510.94 4031.29,1577.61 ; 4031.29,1810.94 4031.29,1827.61 4047.96,1844.28 4031.29,1860.94 4031.29,1877.61 4047.96,1877.61 4064.62,1860.94 4081.29,1877.61 4097.96,1877.61 4097.96,1860.94 4081.29,1844.28 4097.96,1827.61 4097.96,1810.94 4081.29,1810.94 4064.62,1827.61 4047.96,1810.94 4031.29,1810.94 ; 4031.29,1960.94 4097.96,1960.94 4097.96,2027.61 4031.29,2027.61 4031.29,1960.94 ; 4031.29,2127.61 4047.96,2127.61 4064.62,2110.94 4081.29,2127.61 4097.96,2127.61 4081.29,2144.28 4097.96,2160.94 4081.29,2160.94 4064.62,2177.61 4047.96,2160.94 4031.29,2160.94 4047.96,2144.28 4031.29,2127.61 ; 4031.29,2294.28 4064.62,2260.94 4097.96,2294.28 4064.62,2327.61 4031.29,2294.28 ; 4031.29,2477.61 4097.96,2477.61 4064.62,2410.94 4031.29,2477.61 ; 4031.29,2577.61 4047.96,2577.61 4064.62,2560.94 4081.29,2577.61 4097.96,2577.61 4081.29,2594.27 4097.96,2610.94 4081.29,2610.94 4064.62,2627.61 4047.96,2610.94 4031.29,2610.94 4047.96,2594.27 4031.29,2577.61 ; 4031.29,2710.94 4064.62,2727.61 4097.96,2710.94 4081.29,2744.27 4097.96,2777.61 4064.62,2760.94 4031.29,2777.61 4047.96,2744.27 4031.29,2710.94 ; 4031.29,2877.61 4047.96,2877.61 4047.96,2860.94 4081.29,2860.94 4081.29,2877.61 4097.96,2877.61 4097.96,2910.94 4081.29,2910.94 4081.29,2927.61 4047.96,2927.61 4047.96,2910.94 4031.29,2910.94 4031.29,2877.61 ; 4044.62,1564.28 4084.62,1564.28 4064.62,1524.28 4044.62,1564.28 ; 4044.62,1974.28 4084.62,1974.28 4084.62,2014.28 4044.62,2014.28 4044.62,1974.28 ; 4044.62,2134.28 4054.62,2134.28 4064.62,2124.28 4074.62,2134.28 4084.62,2134.28 4074.62,2144.28 4084.62,2154.28 4074.62,2154.28 4064.62,2164.28 4054.62,2154.28 4044.62,2154.28 4054.62,2144.28 4044.62,2134.28
  lines w15: 3971.5,1315.94 9056.11,1315.94 ; 3971.5,3115.94 9056.11,3115.94 ; 4522.38,1165.94 4522.38,3265.94 ; 5122.22,1165.94 5122.22,3265.94 ; 6271.88,1165.94 6271.88,3265.94 ; 6777.76,1165.94 6777.76,3265.94 ; 7511.56,1165.94 7511.56,3265.94 ; 3971.5,1165.94 9056.11,1165.94 9056.11,3265.94 3971.5,3265.94 3971.5,1165.94
  text "Symbol" at 4061.5,3160.94 h72
  text "Count" at 4567.38,3160.94 h72
  text "Hole Size" at 5167.22,3160.94 h72
  text "Plated" at 6316.88,3160.94 h72
  text "Hole Type" at 6822.76,3160.94 h72
  text "Drill Layer Pair" at 7556.56,3160.94 h72
  text "5" at 4567.38,3010.94 h60
  text "7.87mil (0.200mm)" at 5167.22,3010.94 h60
  text "PTH" at 6316.88,3010.94 h60
  text "Round" at 6822.76,3010.94 h60
  text "Top Layer - Bottom Layer" at 7556.56,3010.94 h60
  text "9" at 4567.38,2860.94 h60
  text "8.00mil (0.203mm)" at 5167.22,2860.94 h60
  text "PTH" at 6316.88,2860.94 h60
  text "Round" at 6822.76,2860.94 h60
  text "Top Layer - Bottom Layer" at 7556.56,2860.94 h60
  text "56" at 4567.38,2710.94 h60
  text "12.00mil (0.305mm)" at 5167.22,2710.94 h60
  text "PTH" at 6316.88,2710.94 h60
  text "Round" at 6822.76,2710.94 h60
  text "Top Layer - Bottom Layer" at 7556.56,2710.94 h60
  text "58" at 4567.38,2560.94 h60
  text "16.00mil (0.406mm)" at 5167.22,2560.94 h60
  text "PTH" at 6316.88,2560.94 h60
  text "Round" at 6822.76,2560.94 h60
  text "Top Layer - Bottom Layer" at 7556.56,2560.94 h60
  text "56" at 4567.38,2410.94 h60
  text "20.00mil (0.508mm)" at 5167.22,2410.94 h60
  text "PTH" at 6316.88,2410.94 h60
  text "Round" at 6822.76,2410.94 h60
  text "Top Layer - Bottom Layer" at 7556.56,2410.94 h60
  text "2" at 4567.38,2260.94 h60
  text "31.00mil (0.787mm)" at 5167.22,2260.94 h60
  text "PTH" at 6316.88,2260.94 h60
  text "Round" at 6822.76,2260.94 h60
  text "Top Layer - Bottom Layer" at 7556.56,2260.94 h60
  text "9" at 4567.38,2110.94 h60
  text "32.00mil (0.813mm)" at 5167.22,2110.94 h60
  text "NPTH" at 6316.88,2110.94 h60
  text "Slot" at 6822.76,2110.94 h60
  text "Top Layer - Bottom Layer" at 7556.56,2110.94 h60
  text "3" at 4567.38,1960.94 h60
  text "39.37mil (1.000mm)" at 5167.22,1960.94 h60
  text "PTH" at 6316.88,1960.94 h60
  text "Round" at 6822.76,1960.94 h60
  text "Top Layer - Bottom Layer" at 7556.56,1960.94 h60
  text "8" at 4567.38,1810.94 h60
  text "40.00mil (1.016mm)" at 5167.22,1810.94 h60
  text "PTH" at 6316.88,1810.94 h60
  text "Round" at 6822.76,1810.94 h60
  text "Top Layer - Bottom Layer" at 7556.56,1810.94 h60
  text "20" at 4567.38,1660.94 h60
  text "43.31mil (1.100mm)" at 5167.22,1660.94 h60
  text "PTH" at 6316.88,1660.94 h60
  text "Round" at 6822.76,1660.94 h60
  text "Top Layer - Bottom Layer" at 7556.56,1660.94 h60
  text "2" at 4567.38,1510.94 h60
  text "49.21mil (1.250mm)" at 5167.22,1510.94 h60
  text "PTH" at 6316.88,1510.94 h60
  text "Round" at 6822.76,1510.94 h60
  text "Top Layer - Bottom Layer" at 7556.56,1510.94 h60
  text "4" at 4567.38,1360.94 h60
  text "125.98mil (3.200mm)" at 5167.22,1360.94 h60
  text "PTH" at 6316.88,1360.94 h60
  text "Round" at 6822.76,1360.94 h60
  text "Top Layer - Bottom Layer" at 7556.56,1360.94 h60
  text "232 Total" at 4567.38,1210.94 h60
  text "Slot definitions :" at 4061.5,1065.97 h60
  text "Routed Path Length" at 5094.19,1065.97 h60
  text "= Calculated from tool start centre position to tool end centre position." at 6196.86,1065.97 h60
  text "Hole Length" at 5094.19,965.99 h60
  text "= Routed Path Length + Tool Size = Slot length as defined in the PCB layout" at 5786.99,965.99 h60
  text "Drill Table" at 4350,785 h60
  text "FOR 7.87MIL DRILL +0/-7.87MIL" at 4348,687.64 h60
  text "FOR 8MIL DRILL +0/-8MIL" at 4348,592.28 h60
  text "FOR 12MIL DRILL +0/-12MIL" at 4348,496.92 h60
  text "FOR 16MIL DRILL +0/-16MIL" at 4348,401.57 h60
  text "FOR PTH DRILL +/-3MIL" at 4348,306.21 h60
  text "FOR NPTH DRILL +/-2MIL" at 4348,210.85 h60
  text ".Layer_Name" at 772,-858.49 h60

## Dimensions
0,3089 to 2685,3089 on M2 Board Dimensions
2685,0 to 2685,3089 on M2 Board Dimensions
